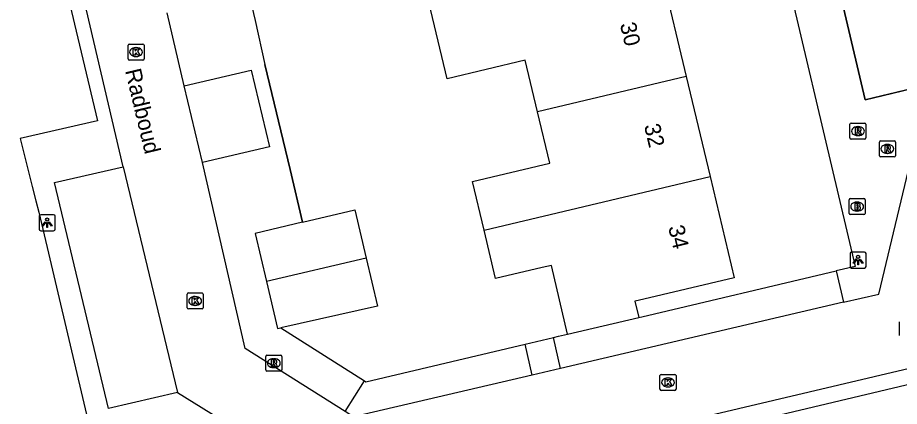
# Model space of a CAD drawing. Extents: x 157663 to 158496, y 379212 to 380934.
# Drawn here: x 158230.6 to 158285.6, y 380832.6 to 380856.9 of the extents above; entities that cross this region are included whole.
import ezdxf

# ---------------------------------------------------------------- set-up
doc = ezdxf.new("R2010")
doc.units = 0
for name, color, linetype in [('IMGEO_Brandkraan', 7, 'Continuous'), ('IMGEO_Hek', 7, 'Continuous'), ('IMGEO_Kolk', 7, 'Continuous'), ('IMGEO_Lichtpunt', 7, 'Continuous'), ('IMGEO_Muur', 7, 'Continuous'), ('IMGEO_Openbare_ruimte_label', 7, 'Continuous'), ('IMGEO_Pand', 7, 'Continuous'), ('IMGEO_Pand_nummerreeks', 7, 'Continuous'), ('IMGEO_Parkeervlak_open', 7, 'Continuous'), ('IMGEO_Rijbaan_lokaal_open', 7, 'Continuous'), ('IMGEO_Rioolput', 7, 'Continuous'), ('IMGEO_Voetpad_open', 7, 'Continuous')]:
    doc.layers.add(name, color=color, linetype=linetype)

msp = doc.modelspace()

# ---------------------------------------------------------------- linework, layer by layer
at = {"layer": 'IMGEO_Brandkraan'}
for p, q in [((158282.482, 380844.632), (158282.482, 380845.484)), ((158282.557, 380845.558), (158283.409, 380845.558)), ((158282.97, 380845.338), (158282.995, 380845.338)), ((158283.483, 380845.484), (158283.483, 380844.632)), ((158282.993, 380844.778), (158282.968, 380844.778)), ((158283.409, 380844.558), (158282.557, 380844.558))]:
    msp.add_line(p, q, dxfattribs=at)
for points in [[(158282.482, 380844.632), (158282.482, 380845.484)], [(158282.557, 380845.558), (158283.409, 380845.558)], [(158282.83, 380845.258), (158282.83, 380844.858), (158283.043, 380844.858)], [(158283.061, 380845.258), (158282.83, 380845.258)], [(158283.009, 380845.177), (158282.955, 380845.177), (158282.955, 380845.101)], [(158283.483, 380845.484), (158283.483, 380844.632)], [(158282.955, 380845.101), (158283.008, 380845.101)], [(158283.017, 380845.025), (158282.955, 380845.025), (158282.955, 380844.944)], [(158282.955, 380844.944), (158283.017, 380844.944)], [(158283.409, 380844.558), (158282.557, 380844.558)]]:
    msp.add_lwpolyline(points, dxfattribs=at)
for centre, radius, start, end in [((158282.559, 380845.482), 0.0765, 91.552, 178.448), ((158282.559, 380845.482), 0.0765, 91.552, 178.448), ((158283.01, 380845.139), 0.0379, 267.8285, 90.9355), ((158283.065, 380845.113), 0.145, 59.4692, 91.5367), ((158283.09, 380845.16), 0.0922, 285.5137, 58.1501), ((158283.407, 380845.482), 0.0765, 1.552, 88.448), ((158283.407, 380845.482), 0.0765, 1.552, 88.448), ((158282.559, 380844.634), 0.0765, 181.552, 268.448), ((158282.559, 380844.634), 0.0765, 181.552, 268.448), ((158283.018, 380844.984), 0.0404, 269.8759, 90.5077), ((158283.049, 380845.109), 0.251, 268.6676, 293.5347), ((158283.095, 380844.968), 0.105, 301.3115, 78.989), ((158283.407, 380844.634), 0.0765, 271.552, 358.448), ((158283.407, 380844.634), 0.0765, 271.552, 358.448)]:
    msp.add_arc(centre, radius, start, end, dxfattribs=at)
for centre, major_axis, ratio, start_param, end_param in [((158282.969, 380845.058), (-0.387, 0.002), 0.722429, 4.712389, 7.853982), ((158282.994, 380845.058), (-0.39, 0.002), 0.717154, 1.570796, 4.712389)]:
    msp.add_ellipse(centre, major_axis=major_axis, ratio=ratio, start_param=start_param, end_param=end_param, dxfattribs=at)
at = {"layer": 'IMGEO_Hek'}
for points in [[(158284.011, 380851.861), (158283.487, 380851.735), (158280.865, 380862.903)], [(158296.964, 380854.965), (158284.011, 380851.861)], [(158248.365, 380844.076), (158247.588, 380847.376)], [(158247.001, 380837.483), (158252.238, 380834.159)], [(158262.259, 380836.459), (158264.02, 380836.875)], [(158264.02, 380836.875), (158264.34, 380836.951)], [(158264.34, 380836.951), (158264.902, 380837.084)], [(158252.238, 380834.159), (158252.315, 380834.11), (158262.259, 380836.459)]]:
    msp.add_lwpolyline(points, dxfattribs=at)
at = {"layer": 'IMGEO_Kolk'}
for p, q in [((158237.465, 380854.286), (158237.465, 380855.138)), ((158237.54, 380855.212), (158238.392, 380855.212)), ((158238.466, 380855.138), (158238.466, 380854.286)), ((158237.953, 380854.992), (158237.978, 380854.992)), ((158238.392, 380854.212), (158237.54, 380854.212)), ((158237.976, 380854.432), (158237.951, 380854.432)), ((158241.234, 380839.656), (158242.086, 380839.656)), ((158241.159, 380838.73), (158241.159, 380839.582)), ((158241.647, 380839.436), (158241.672, 380839.436)), ((158242.16, 380839.582), (158242.16, 380838.73)), ((158242.086, 380838.656), (158241.234, 380838.656)), ((158241.67, 380838.876), (158241.645, 380838.876)), ((158270.675, 380833.639), (158270.675, 380834.491)), ((158270.75, 380834.565), (158271.602, 380834.565)), ((158271.163, 380834.345), (158271.188, 380834.345)), ((158271.676, 380834.491), (158271.676, 380833.639)), ((158271.602, 380833.565), (158270.75, 380833.565)), ((158271.186, 380833.785), (158271.161, 380833.785))]:
    msp.add_line(p, q, dxfattribs=at)
for points in [[(158237.465, 380854.286), (158237.465, 380855.138)], [(158237.54, 380855.212), (158238.392, 380855.212)], [(158238.466, 380855.138), (158238.466, 380854.286)], [(158237.786, 380854.912), (158237.909, 380854.912), (158237.909, 380854.761), (158238.039, 380854.912), (158238.203, 380854.912), (158238.057, 380854.761), (158238.21, 380854.512), (158238.058, 380854.512), (158237.973, 380854.676), (158237.909, 380854.609), (158237.909, 380854.512), (158237.786, 380854.512), (158237.786, 380854.912)], [(158238.392, 380854.212), (158237.54, 380854.212)], [(158241.234, 380839.656), (158242.086, 380839.656)], [(158241.159, 380838.73), (158241.159, 380839.582)], [(158241.48, 380839.356), (158241.603, 380839.356), (158241.603, 380839.205), (158241.733, 380839.356), (158241.897, 380839.356), (158241.751, 380839.205), (158241.904, 380838.956), (158241.752, 380838.956), (158241.667, 380839.12), (158241.603, 380839.053), (158241.603, 380838.956), (158241.48, 380838.956), (158241.48, 380839.356)], [(158242.16, 380839.582), (158242.16, 380838.73)], [(158242.086, 380838.656), (158241.234, 380838.656)], [(158270.675, 380833.639), (158270.675, 380834.491)], [(158270.75, 380834.565), (158271.602, 380834.565)], [(158270.996, 380834.265), (158271.119, 380834.265), (158271.119, 380834.114), (158271.249, 380834.265), (158271.413, 380834.265), (158271.267, 380834.114), (158271.42, 380833.865), (158271.268, 380833.865), (158271.183, 380834.029), (158271.119, 380833.962), (158271.119, 380833.865), (158270.996, 380833.865), (158270.996, 380834.265)], [(158271.676, 380834.491), (158271.676, 380833.639)], [(158271.602, 380833.565), (158270.75, 380833.565)]]:
    msp.add_lwpolyline(points, dxfattribs=at)
for centre, start, end in [((158237.542, 380855.136), 91.552, 178.448), ((158237.542, 380855.136), 91.552, 178.448), ((158238.39, 380855.136), 1.552, 88.448), ((158238.39, 380855.136), 1.552, 88.448), ((158237.542, 380854.288), 181.552, 268.448), ((158237.542, 380854.288), 181.552, 268.448), ((158238.39, 380854.288), 271.552, 358.448), ((158238.39, 380854.288), 271.552, 358.448), ((158241.236, 380839.58), 91.552, 178.448), ((158241.236, 380839.58), 91.552, 178.448), ((158242.084, 380839.58), 1.552, 88.448), ((158242.084, 380839.58), 1.552, 88.448), ((158241.236, 380838.732), 181.552, 268.448), ((158241.236, 380838.732), 181.552, 268.448), ((158242.084, 380838.732), 271.552, 358.448), ((158242.084, 380838.732), 271.552, 358.448), ((158270.752, 380834.489), 91.552, 178.448), ((158270.752, 380834.489), 91.552, 178.448), ((158271.6, 380834.489), 1.552, 88.448), ((158271.6, 380834.489), 1.552, 88.448), ((158270.752, 380833.641), 181.552, 268.448), ((158270.752, 380833.641), 181.552, 268.448), ((158271.6, 380833.641), 271.552, 358.448), ((158271.6, 380833.641), 271.552, 358.448)]:
    msp.add_arc(centre, 0.0765, start, end, dxfattribs=at)
for centre, major_axis, ratio, start_param, end_param in [((158237.952, 380854.712), (-0.387, 0.002), 0.722429, 4.712389, 7.853982), ((158237.977, 380854.712), (-0.39, 0.002), 0.717154, 1.570796, 4.712389), ((158241.646, 380839.156), (-0.387, 0.002), 0.722429, 4.712389, 7.853982), ((158241.671, 380839.156), (-0.39, 0.002), 0.717154, 1.570796, 4.712389), ((158271.162, 380834.065), (-0.387, 0.002), 0.722429, 4.712389, 7.853982), ((158271.187, 380834.065), (-0.39, 0.002), 0.717154, 1.570796, 4.712389)]:
    msp.add_ellipse(centre, major_axis=major_axis, ratio=ratio, start_param=start_param, end_param=end_param, dxfattribs=at)
at = {"layer": 'IMGEO_Lichtpunt'}
for p, q in [((158231.921, 380844.449), (158231.921, 380843.642)), ((158231.921, 380844.449), (158231.921, 380843.642)), ((158232.823, 380844.544), (158232.015, 380844.544)), ((158232.823, 380844.544), (158232.015, 380844.544)), ((158232.917, 380843.642), (158232.917, 380844.449)), ((158232.917, 380843.642), (158232.917, 380844.449)), ((158232.015, 380843.548), (158232.823, 380843.548)), ((158232.015, 380843.548), (158232.823, 380843.548)), ((158282.543, 380842.117), (158282.543, 380841.31)), ((158282.543, 380842.117), (158282.543, 380841.31)), ((158283.445, 380842.212), (158282.637, 380842.212)), ((158283.445, 380842.212), (158282.637, 380842.212)), ((158283.539, 380841.31), (158283.539, 380842.117)), ((158283.539, 380841.31), (158283.539, 380842.117)), ((158282.637, 380841.216), (158283.445, 380841.216)), ((158282.637, 380841.216), (158283.445, 380841.216))]:
    msp.add_line(p, q, dxfattribs=at)
for points in [[(158232.295, 380844.113), (158232.334, 380844.085), (158232.146, 380843.823), (158232.108, 380843.85), (158232.295, 380844.113)], [(158232.397, 380844.065), (158232.444, 380844.065), (158232.444, 380843.743), (158232.397, 380843.743), (158232.397, 380844.065)], [(158232.507, 380844.085), (158232.545, 380844.112), (158232.732, 380843.85), (158232.693, 380843.822), (158232.507, 380844.085)], [(158282.917, 380841.781), (158282.956, 380841.753), (158282.768, 380841.491), (158282.73, 380841.518), (158282.917, 380841.781)], [(158283.019, 380841.733), (158283.066, 380841.733), (158283.066, 380841.411), (158283.019, 380841.411), (158283.019, 380841.733)], [(158283.129, 380841.753), (158283.167, 380841.78), (158283.354, 380841.518), (158283.315, 380841.49), (158283.129, 380841.753)]]:
    msp.add_lwpolyline(points, dxfattribs=at)
for centre in [(158232.42, 380844.247), (158283.042, 380841.915)]:
    msp.add_circle(centre, 0.0994, dxfattribs=at)
for centre, start, end in [((158232.015, 380844.449), 90, 180), ((158232.015, 380844.449), 90, 180), ((158232.823, 380844.449), 0, 90), ((158232.823, 380844.449), 0, 90), ((158232.015, 380843.642), 180, 270), ((158232.015, 380843.642), 180, 270), ((158232.823, 380843.642), 270, 0), ((158232.823, 380843.642), 270, 360), ((158282.637, 380842.117), 90, 180), ((158282.637, 380842.117), 90, 180), ((158283.445, 380842.117), 0, 90), ((158283.445, 380842.117), 0, 90), ((158282.637, 380841.31), 180, 270), ((158282.637, 380841.31), 180, 270), ((158283.445, 380841.31), 270, 0), ((158283.445, 380841.31), 270, 360)]:
    msp.add_arc(centre, 0.0946, start, end, dxfattribs=at)
at = {"layer": 'IMGEO_Muur'}
msp.add_lwpolyline([(158247.588, 380847.376), (158245.997, 380853.936)], dxfattribs=at)
at = {"layer": 'IMGEO_Pand'}
for points in [[(158263.087, 380860.905), (158263.797, 380857.918), (158264.237, 380858.023), (158270.794, 380859.582), (158272.313, 380853.194)], [(158263.027, 380850.988), (158262.262, 380854.204), (158257.394, 380853.046), (158255.921, 380859.242)], [(158272.313, 380853.194), (158263.027, 380850.988)], [(158272.313, 380853.194), (158273.799, 380846.941)], [(158259.695, 380843.59), (158258.974, 380846.624), (158263.792, 380847.77), (158263.027, 380850.988)], [(158259.695, 380843.59), (158273.799, 380846.941)], [(158273.799, 380846.941), (158275.308, 380840.596), (158269.304, 380839.186), (158269.109, 380839.14), (158269.347, 380838.127)], [(158248.365, 380844.076), (158251.626, 380844.844), (158252.334, 380841.837)], [(158248.365, 380844.076), (158245.396, 380843.377), (158246.104, 380840.37)], [(158264.902, 380837.084), (158263.893, 380841.381), (158263.319, 380841.244), (158260.417, 380840.554), (158259.695, 380843.59)], [(158252.334, 380841.837), (158246.104, 380840.37)], [(158252.334, 380841.837), (158253.042, 380838.831), (158247.001, 380837.483)], [(158246.104, 380840.37), (158246.795, 380837.437), (158247.001, 380837.483)], [(158264.902, 380837.084), (158269.347, 380838.127)]]:
    msp.add_lwpolyline(points, dxfattribs=at)
at = {"layer": 'IMGEO_Parkeervlak_open'}
for points in [[(158269.347, 380838.127), (158269.541, 380838.173), (158281.675, 380841.04)], [(158264.02, 380836.875), (158264.34, 380836.951), (158264.902, 380837.084)], [(158252.238, 380834.159), (158252.315, 380834.11), (158262.259, 380836.459)]]:
    msp.add_lwpolyline(points, dxfattribs=at)
at = {"layer": 'IMGEO_Rijbaan_lokaal_open'}
for points in [[(158237.173, 380847.541), (158231.515, 380871.684)], [(158335.841, 380868.585), (158317.438, 380864.207), (158322.34, 380843.453), (158256.423, 380827.895), (158256.672, 380826.915)], [(158240.979, 380852.604), (158239.919, 380857.157)], [(158242.114, 380847.802), (158240.979, 380852.604)], [(158282.13, 380839.078), (158284.341, 380839.582), (158287.237, 380851.686)], [(158237.173, 380847.541), (158240.548, 380833.44)], [(158251.024, 380832.251), (158244.769, 380836.177), (158242.114, 380847.802)], [(158282.13, 380839.078), (158264.466, 380834.939)], [(158264.466, 380834.939), (158262.698, 380834.525)], [(158262.698, 380834.525), (158251.543, 380831.91), (158251.024, 380832.251)], [(158240.548, 380833.44), (158244.724, 380830.856)]]:
    msp.add_lwpolyline(points, dxfattribs=at)
at = {"layer": 'IMGEO_Rioolput'}
for p, q in [((158282.532, 380849.346), (158282.532, 380850.198)), ((158282.607, 380850.272), (158283.459, 380850.272)), ((158283.533, 380850.198), (158283.533, 380849.346)), ((158283.02, 380850.052), (158283.045, 380850.052)), ((158283.459, 380849.272), (158282.607, 380849.272)), ((158283.043, 380849.492), (158283.018, 380849.492)), ((158284.372, 380848.234), (158284.372, 380849.086)), ((158284.447, 380849.16), (158285.299, 380849.16)), ((158285.373, 380849.086), (158285.373, 380848.234)), ((158284.86, 380848.94), (158284.885, 380848.94)), ((158285.299, 380848.16), (158284.447, 380848.16)), ((158284.883, 380848.38), (158284.858, 380848.38)), ((158285.619, 380837.001), (158285.619, 380837.853)), ((158246.141, 380835.77), (158246.993, 380835.77)), ((158246.066, 380834.844), (158246.066, 380835.696)), ((158246.554, 380835.55), (158246.579, 380835.55)), ((158247.067, 380835.696), (158247.067, 380834.844)), ((158246.993, 380834.77), (158246.141, 380834.77)), ((158246.577, 380834.99), (158246.552, 380834.99))]:
    msp.add_line(p, q, dxfattribs=at)
for points in [[(158282.532, 380849.346), (158282.532, 380850.198)], [(158282.607, 380850.272), (158283.459, 380850.272)], [(158283.533, 380850.198), (158283.533, 380849.346)], [(158283.121, 380849.97), (158282.869, 380849.972), (158282.869, 380849.572)], [(158282.869, 380849.572), (158282.993, 380849.572), (158282.993, 380849.734), (158283.004, 380849.734)], [(158283.047, 380849.891), (158282.993, 380849.891), (158282.993, 380849.81)], [(158282.993, 380849.81), (158283.045, 380849.81)], [(158283.051, 380849.705), (158283.122, 380849.572), (158283.262, 380849.572), (158283.197, 380849.698)], [(158283.459, 380849.272), (158282.607, 380849.272)], [(158284.372, 380848.234), (158284.372, 380849.086)], [(158284.447, 380849.16), (158285.299, 380849.16)], [(158285.373, 380849.086), (158285.373, 380848.234)], [(158284.961, 380848.858), (158284.709, 380848.86), (158284.709, 380848.46)], [(158284.709, 380848.46), (158284.833, 380848.46), (158284.833, 380848.622), (158284.844, 380848.622)], [(158284.887, 380848.779), (158284.833, 380848.779), (158284.833, 380848.698)], [(158284.833, 380848.698), (158284.885, 380848.698)], [(158284.891, 380848.593), (158284.962, 380848.46), (158285.102, 380848.46), (158285.037, 380848.586)], [(158285.299, 380848.16), (158284.447, 380848.16)], [(158285.619, 380837.001), (158285.619, 380837.853)], [(158246.141, 380835.77), (158246.993, 380835.77)], [(158246.066, 380834.844), (158246.066, 380835.696)], [(158246.655, 380835.468), (158246.403, 380835.47), (158246.403, 380835.07)], [(158246.403, 380835.07), (158246.527, 380835.07), (158246.527, 380835.232), (158246.538, 380835.232)], [(158246.581, 380835.389), (158246.527, 380835.389), (158246.527, 380835.308)], [(158246.527, 380835.308), (158246.579, 380835.308)], [(158247.067, 380835.696), (158247.067, 380834.844)], [(158246.993, 380834.77), (158246.141, 380834.77)], [(158246.585, 380835.203), (158246.656, 380835.07), (158246.796, 380835.07), (158246.731, 380835.196)]]:
    msp.add_lwpolyline(points, dxfattribs=at)
for centre, radius, start, end in [((158282.609, 380850.196), 0.0765, 91.552, 178.448), ((158282.609, 380850.196), 0.0765, 91.552, 178.448), ((158283.457, 380850.196), 0.0765, 1.552, 88.448), ((158283.457, 380850.196), 0.0765, 1.552, 88.448), ((158283.003, 380849.681), 0.0533, 26.0293, 88.6989), ((158283.029, 380849.999), 0.19, 274.7715, 282.9687), ((158283.053, 380849.795), 0.0964, 77.0061, 93.1865), ((158283.067, 380849.852), 0.0378, 276.6634, 79.6772), ((158283.12, 380849.86), 0.109, 350.3612, 89.416), ((158283.118, 380849.86), 0.112, 277.5842, 350.9817), ((158283.102, 380849.645), 0.108, 29.5134, 73.7905), ((158282.609, 380849.348), 0.0765, 181.552, 268.448), ((158282.609, 380849.348), 0.0765, 181.552, 268.448), ((158283.457, 380849.348), 0.0765, 271.552, 358.448), ((158283.457, 380849.348), 0.0765, 271.552, 358.448), ((158284.449, 380849.084), 0.0765, 91.552, 178.448), ((158284.449, 380849.084), 0.0765, 91.552, 178.448), ((158285.297, 380849.084), 0.0765, 1.552, 88.448), ((158285.297, 380849.084), 0.0765, 1.552, 88.448), ((158284.843, 380848.569), 0.0533, 26.0293, 88.6989), ((158284.869, 380848.887), 0.19, 274.7715, 282.9687), ((158284.893, 380848.683), 0.0964, 77.0061, 93.1865), ((158284.907, 380848.74), 0.0378, 276.6634, 79.6772), ((158284.96, 380848.748), 0.109, 350.3612, 89.416), ((158284.958, 380848.748), 0.112, 277.5842, 350.9817), ((158284.942, 380848.533), 0.108, 29.5134, 73.7905), ((158284.449, 380848.236), 0.0765, 181.552, 268.448), ((158284.449, 380848.236), 0.0765, 181.552, 268.448), ((158285.297, 380848.236), 0.0765, 271.552, 358.448), ((158285.297, 380848.236), 0.0765, 271.552, 358.448), ((158246.143, 380835.694), 0.0765, 91.552, 178.448), ((158246.143, 380835.694), 0.0765, 91.552, 178.448), ((158246.991, 380835.694), 0.0765, 1.552, 88.448), ((158246.991, 380835.694), 0.0765, 1.552, 88.448), ((158246.537, 380835.179), 0.0533, 26.0293, 88.6989), ((158246.563, 380835.497), 0.19, 274.7715, 282.9687), ((158246.587, 380835.293), 0.0964, 77.0061, 93.1865), ((158246.601, 380835.35), 0.0378, 276.6634, 79.6772), ((158246.654, 380835.358), 0.109, 350.3612, 89.416), ((158246.652, 380835.358), 0.112, 277.5842, 350.9817), ((158246.636, 380835.143), 0.108, 29.5134, 73.7905), ((158246.143, 380834.846), 0.0765, 181.552, 268.448), ((158246.143, 380834.846), 0.0765, 181.552, 268.448), ((158246.991, 380834.846), 0.0765, 271.552, 358.448), ((158246.991, 380834.846), 0.0765, 271.552, 358.448)]:
    msp.add_arc(centre, radius, start, end, dxfattribs=at)
for centre, major_axis, ratio, start_param, end_param in [((158283.019, 380849.772), (-0.387, 0.002), 0.722429, 4.712389, 7.853982), ((158283.044, 380849.772), (-0.39, 0.002), 0.717154, 1.570796, 4.712389), ((158284.859, 380848.66), (-0.387, 0.002), 0.722429, 4.712389, 7.853982), ((158284.884, 380848.66), (-0.39, 0.002), 0.717154, 1.570796, 4.712389), ((158246.553, 380835.27), (-0.387, 0.002), 0.722429, 4.712389, 7.853982), ((158246.578, 380835.27), (-0.39, 0.002), 0.717154, 1.570796, 4.712389)]:
    msp.add_ellipse(centre, major_axis=major_axis, ratio=ratio, start_param=start_param, end_param=end_param, dxfattribs=at)
at = {"layer": 'IMGEO_Voetpad_open'}
for points in [[(158268.406, 380889.479), (158274.546, 380863.519), (158277.477, 380864.209), (158282.851, 380841.317), (158281.675, 380841.04)], [(158271.67, 380888.542), (158276.061, 380869.995), (158278.992, 380870.719), (158280.865, 380862.903), (158283.487, 380851.735), (158284.011, 380851.861), (158287.022, 380852.583)], [(158231.515, 380871.684), (158230.575, 380871.461), (158235.571, 380850.422), (158230.728, 380849.308), (158231.486, 380846.302), (158231.719, 380845.417), (158231.903, 380844.699), (158234.881, 380832.061)], [(158244.802, 380859.24), (158245.406, 380856.682), (158245.997, 380853.936), (158247.588, 380847.376), (158248.365, 380844.076)], [(158240.979, 380852.604), (158245.164, 380853.578), (158246.294, 380848.786), (158242.114, 380847.802)], [(158236.255, 380832.428), (158232.868, 380846.559), (158237.173, 380847.541)], [(158321.058, 380841.488), (158320.897, 380842.175), (158312.07, 380840.074), (158256.672, 380826.915)], [(158281.675, 380841.04), (158282.13, 380839.078)], [(158247.001, 380837.483), (158252.238, 380834.159)], [(158262.259, 380836.459), (158264.02, 380836.875)], [(158264.466, 380834.939), (158264.02, 380836.875)], [(158262.698, 380834.525), (158262.259, 380836.459)], [(158251.024, 380832.251), (158252.238, 380834.159)], [(158240.548, 380833.44), (158236.255, 380832.428)]]:
    msp.add_lwpolyline(points, dxfattribs=at)

# ---------------------------------------------------------------- texts
at = {"layer": 'IMGEO_Openbare_ruimte_label'}
msp.add_text('Radboud', height=1, rotation=283.4111, dxfattribs=at).set_placement((158237.276, 380853.557))
at = {"layer": 'IMGEO_Pand_nummerreeks'}
for s, p in [('30', (158268.166, 380856.453)), ('32', (158269.672, 380850.117)), ('34', (158271.181, 380843.773))]:
    msp.add_text(s, height=1, rotation=283.3732, dxfattribs=at).set_placement(p)

doc.saveas('drawing.dxf')
